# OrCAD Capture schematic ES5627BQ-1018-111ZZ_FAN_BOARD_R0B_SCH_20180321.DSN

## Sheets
1 P03 FAN Board: size B; title: ES5627BQ-1018-111ZZ; rev: R0A
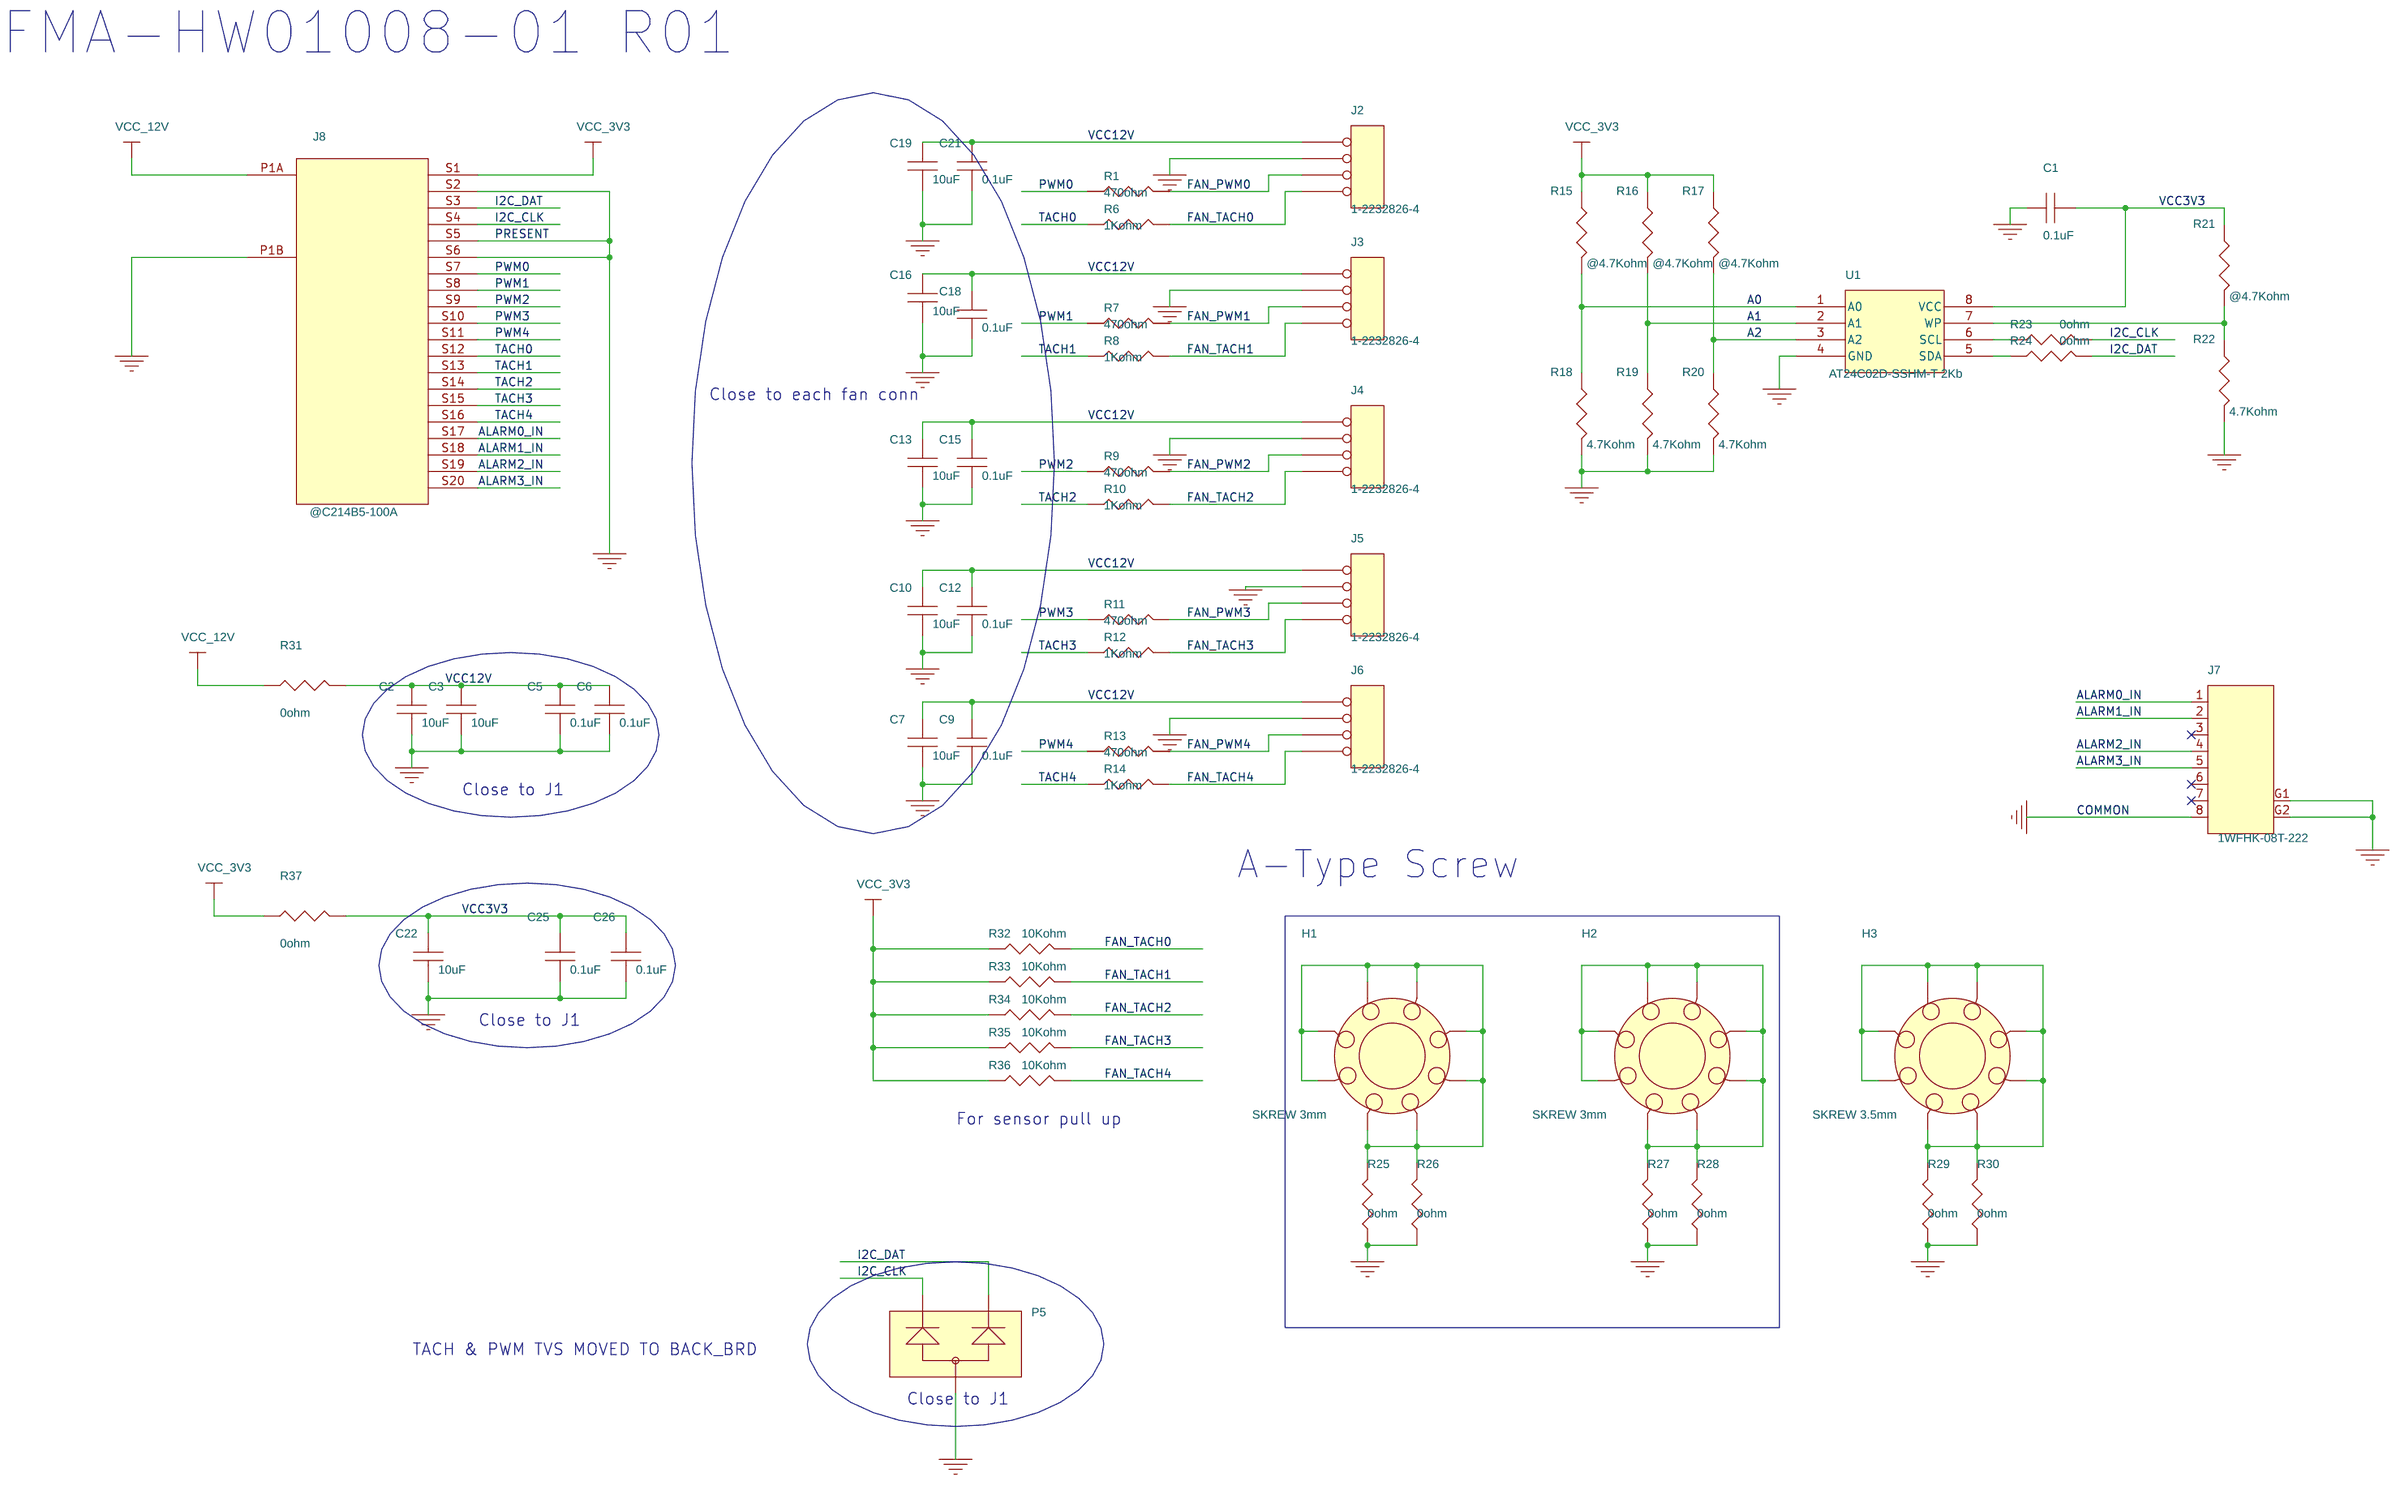
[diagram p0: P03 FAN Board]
2 P02 Revision History
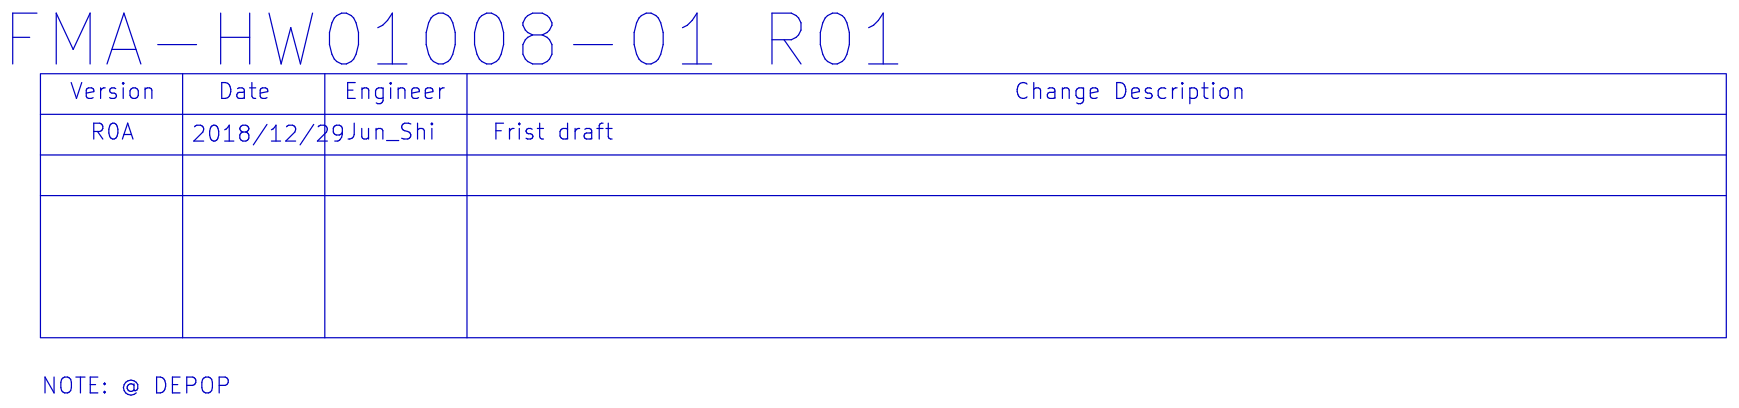
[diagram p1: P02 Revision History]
3 P01 Block
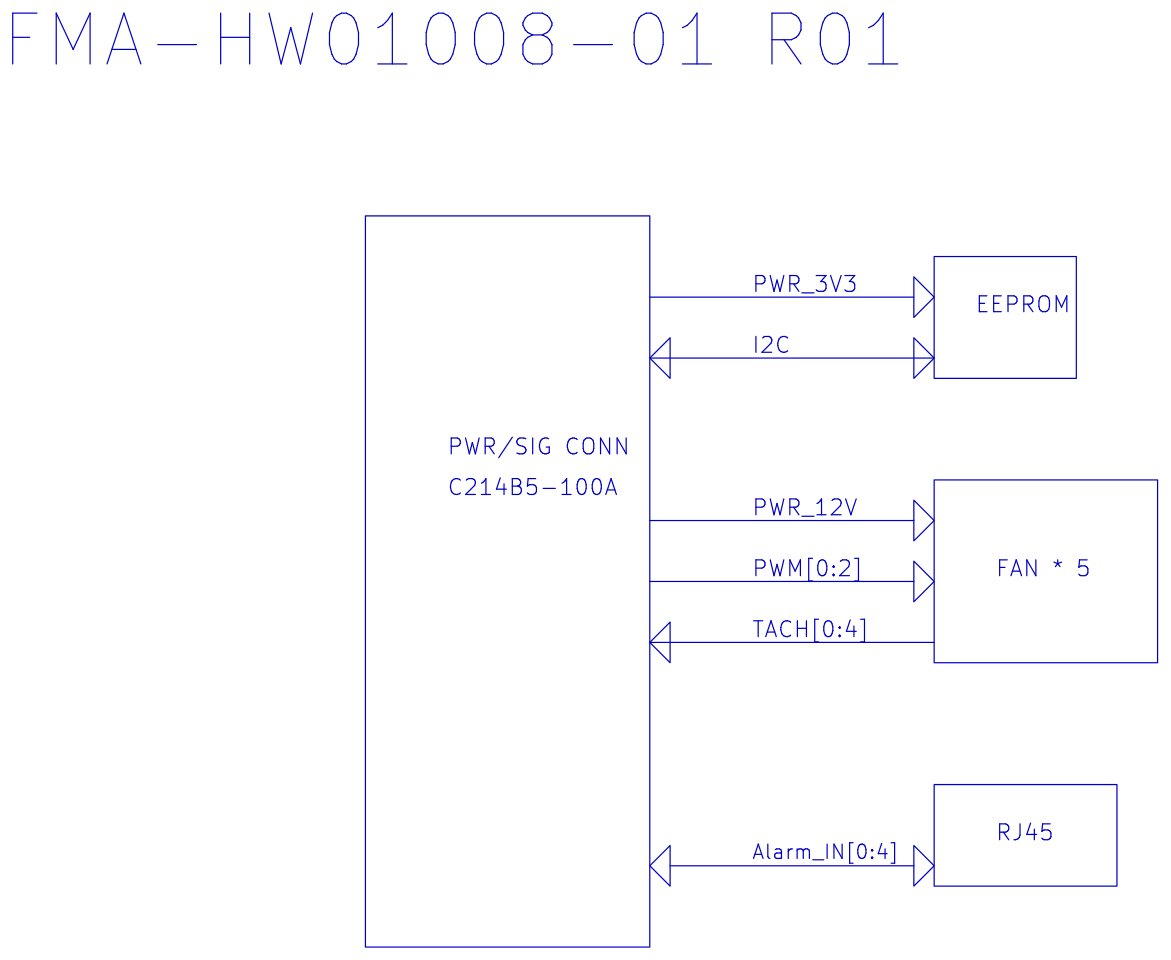
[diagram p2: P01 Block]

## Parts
C1  0.1uF  [CC0402]
C2  10uF  [CC1206]
C3  10uF  [CC1206]
C5  0.1uF  [CC0402]
C6  0.1uF  [CC0402]
C7  10uF  [CC1206]
C9  0.1uF  [CC0402]
C10  10uF  [CC1206]
C12  0.1uF  [CC0402]
C13  10uF  [CC1206]
C15  0.1uF  [CC0402]
C16  10uF  [CC1206]
C18  0.1uF  [CC0402]
C19  10uF  [CC1206]
C21  0.1uF  [CC0402]
C22  10uF  [CC1206]
C25  0.1uF  [CC0402]
C26  0.1uF  [CC0402]
H1  SKREW 3mm  [mth_276c118d_8dp_osp]
H2  SKREW 3mm  [mth_276c118d_8dp_osp]
H3  SKREW 3.5mm  [mth_276c138d_8dp_osp]
J2  1-2232826-4  [conn_2d_1x4dp_10d32w7d1l]
J3  1-2232826-4  [conn_2d_1x4dp_10d32w7d1l]
J4  1-2232826-4  [conn_2d_1x4dp_10d32w7d1l]
J5  1-2232826-4  [conn_2d_1x4dp_10d32w7d1l]
J6  1-2232826-4  [conn_2d_1x4dp_10d32w7d1l]
J7  1WFHK-08T-222  [conn_1d_8sp_10w2d9l4d8h]
J8  @C214B5-100A  [gold_finger_1d27_10x2sp_zz]
P5  PSOT03C  [SOT23_1D9X2D_3SP_1D3W2D92L1D11H]
R1  470ohm  [RC0402]
R6  1Kohm  [RC0402]
R7  470ohm  [RC0402]
R8  1Kohm  [RC0402]
R9  470ohm  [RC0402]
R10  1Kohm  [RC0402]
R11  470ohm  [RC0402]
R12  1Kohm  [RC0402]
R13  470ohm  [RC0402]
R14  1Kohm  [RC0402]
R15  @4.7Kohm  [RC0402]
R16  @4.7Kohm  [RC0402]
R17  @4.7Kohm  [RC0402]
R18  4.7Kohm  [RC0402]
R19  4.7Kohm  [RC0402]
R20  4.7Kohm  [RC0402]
R21  @4.7Kohm  [RC0402]
R22  4.7Kohm  [RC0402]
R23  0ohm  [RC0402]
R24  0ohm  [RC0402]
R25  0ohm  [RC0402]
R26  0ohm  [RC0402]
R27  0ohm  [RC0402]
R28  0ohm  [RC0402]
R29  0ohm  [RC0402]
R30  0ohm  [RC0402]
R31  0ohm  [RC1206]
R32  10Kohm  [RC0402]
R33  10Kohm  [RC0402]
R34  10Kohm  [RC0402]
R35  10Kohm  [RC0402]
R36  10Kohm  [RC0402]
R37  0ohm  [RC1206]
U1  AT24C02D-SSHM-T 2Kb  [SOIC_1D27X5D16_8SP_3D9W4D925L]

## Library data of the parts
C1 C5 C6 C9 C12 C15 C18 C21 C25 C26 = C_NP: C SMD CER 0.1uF 10% 16V X7R 0402 T0.5mm; Package Type: 2; Part Number: 2041043KC100E; Part Type: CAP(SMD); Vendor_NO1: ‡ø¾Þ; Vendor_NO2: SAMSUNG; Vendor_NO3: 禾伸堂; Vendor_NO4: 華新
C2 C3 C7 C10 C13 C16 C19 C22 = C_NP: C SMD CER 10uF 10% 16V X7R 1206 T1.6mm; Package Type: 2; Part Number: 204000000077A; Part Type: CAP(SMD); Vendor_NO1: 華新; Vendor_NO2: 禾伸堂; Vendor_NO3: TAIYO; Vendor_NO4: SAMSUNG
H1-H3 = SKREW
J2-J6 = CONN_WAFER_MALE_4PX1R: ?!HEADER BOX 4PX1R P2mm H6.15 180M POST-1 DIP4SP3.0 TE; Package Type: 1; Part Number: 118200001037H; Part Type: HEADER/PIN STICK
J7 = CONN_WAFER_MALE_8PX1R_G2: ?!HEADER BOX 8PX1R P1mm H4.25 180M SMD8 CYBERCONN; Package Type: 2; Part Number: 118200001042H; Part Type: HEADER/PIN STICK
J8 = C214B5-100A_0: Part Number: 118500000437H
P5 = TVS3_1: TVS PSOT03C-LF-T7 3.3V 125uA SOT23 PROTEK(168FB); Package Type: 2; Part Number: 115000000231A; Part Type: DIODE; Vendor_NO1: PROTEK
R1 R7 R9 R11 R13 = R: RES SMD 470ohm 5% 1/16W 0402; Package Type: 2; Part Number: 20047000JN60J; Part Type: RES(SMD); Vendor_NO1: ‡ø¾Þ; Vendor_NO2: 華新
R6 R8 R10 R12 R14 = R: RES SMD 1Kohm 5% 1/16W 0402; Package Type: 2; Part Number: 20010010JN61A; Part Type: RES(SMD); Vendor_NO1: 飛元; Vendor_NO2: ‡ø¾Þ; Vendor_NO3: 華新WALSIN
R15-R22 = R: RES SMD 4.7Kohm 1% 1/16W 0402; Package Type: 2; Part Number: 20047010FN60A; Part Type: RES(SMD); Vendor_NO1: 飛元; Vendor_NO2: ‡ø¾Þ; Vendor_NO3: 華新
R23-R30 = R: RES SMD 0ohm 5% 1/16W 0402; Package Type: 2; Part Number: 20000000JN60A; Part Type: RES(SMD); Vendor_NO1: ‡ø¾Þ; Vendor_NO2: ‡ø¾Þ; Vendor_NO3: 華新; Vendor_NO4: 飛元
R31 R37 = R: RES SMD 0ohm 5% 1/4W 1206; Package Type: 2; Part Number: 20000000JB10E; Part Type: RES(SMD); Vendor_NO1: ‡ø¾Þ; Vendor_NO2: ‡ø¾Þ; Vendor_NO3: 華新; Vendor_NO4: 華新
R32-R36 = R: RES SMD 10Kohm 5% 1/16W 0402; Package Type: 2; Part Number: 20010020JN60A; Part Type: RES(SMD); Vendor_NO1: ‡ø¾Þ; Vendor_NO2: ‡ø¾Þ; Vendor_NO3: 華新; Vendor_NO4: 飛元
U1 = EEPROM_ATMEL_AT24C02D: EEPROM AT24C02D-SSHM-T 2Kb 1.7~3.6V 5ms I2C SOIC8 MICROCHIP; Package Type: 2; Part Number: 107000000061A; Part Type: MEMORY/EEPROM; Vendor_NO1: ATMEL

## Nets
GND: C1.1 C2.2 C3.2 C5.2 C6.2 C7.2 C9.2 C10.2 C12.2 C13.2 C15.2 C16.2 C18.2 C19.2 C21.2 C22.2 C25.2 C26.2 J2.2 J3.2 J4.2 J5.2 J6.2 J7.8 J7.G1 J7.G2 J8.P1B J8.S2 J8.S5 J8.S6 P5.A R18.1 R19.1 R20.1 R22.1 R25.2 R26.2 R27.2 R28.2 R29.2 R30.2 U1.4(GND)
VCC3V3: C1.2 C22.1 C25.1 C26.1 R21.2 R37.1 U1.8(VCC)
VCC12V: C2.1 C3.1 C5.1 C6.1 C7.1 C9.1 C10.1 C12.1 C13.1 C15.1 C16.1 C18.1 C19.1 C21.1 J2.1 J3.1 J4.1 J5.1 J6.1 R31.1
VCC_3V3: J8.S1 R15.2 R16.2 R17.2 R32.2 R33.2 R34.2 R35.2 R36.2 R37.2
VCC_12V: J8.P1A R31.2
A0: R15.1 R18.2 U1.1(A0)
A1: R16.1 R19.2 U1.2(A1)
A2: R17.1 R20.2 U1.3(A2)
ALARM0_IN: J7.1 J8.S17
ALARM1_IN: J7.2 J8.S18
ALARM2_IN: J7.4 J8.S19
ALARM3_IN: J7.5 J8.S20
FAN_PWM0: J2.3 R1.1
FAN_PWM1: J3.3 R7.1
FAN_PWM2: J4.3 R9.1
FAN_PWM3: J5.3 R11.1
FAN_PWM4: J6.3 R13.1
FAN_TACH0: J2.4 R6.1 R32.1
FAN_TACH1: J3.4 R8.1 R33.1
FAN_TACH2: J4.4 R10.1 R34.1
FAN_TACH3: J5.4 R12.1 R35.1
FAN_TACH4: J6.4 R14.1 R36.1
I2C_CLK: J8.S4 P5.C2 R23.1
I2C_DAT: J8.S3 P5.C1 R24.1
PWM0: J8.S7 R1.2
PWM1: J8.S8 R7.2
PWM2: J8.S9 R9.2
PWM3: J8.S10 R11.2
PWM4: J8.S11 R13.2
TACH0: J8.S12 R6.2
TACH1: J8.S13 R8.2
TACH2: J8.S14 R10.2
TACH3: J8.S15 R12.2
TACH4: J8.S16 R14.2
N15562: R21.1 R22.2 U1.7(WP)
N15996: R23.2 U1.6(SCL)
N16000: R24.2 U1.5(SDA)
N16358: H1.1 H1.2 H1.3 H1.4 H1.5 H1.6 H1.7 H1.8 R25.1 R26.1
N20593: H2.1 H2.2 H2.3 H2.4 H2.5 H2.6 H2.7 H2.8 R27.1 R28.1
N20989: H3.1 H3.2 H3.3 H3.4 H3.5 H3.6 H3.7 H3.8 R29.1 R30.1

Not connected (* = marked no-connect by the designer): J7 3* 6* 7*

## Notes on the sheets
sheet 1
- FMA-HW01008-01 R01
- Close to each fan conn
- Close to J1
- A-Type Screw
- Close to J1
- For sensor pull up
- TACH & PWM TVS MOVED TO BACK_BRD
- Close to J1
sheet 2
- FMA-HW01008-01 R01
- Version
- Date
- Engineer
- Change Description
- R0A
- 2018/12/29
- Jun_Shi
- Frist draft
- NOTE: @ DEPOP
sheet 3
- FMA-HW01008-01 R01
- PWR_3V3
- EEPROM
- I2C
- PWR/SIG CONN
- C214B5-100A
- PWR_12V
- PWM[0:2]
- FAN * 5
- TACH[0:4]
- RJ45
- Alarm_IN[0:4]
